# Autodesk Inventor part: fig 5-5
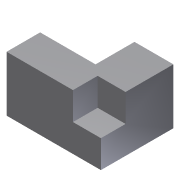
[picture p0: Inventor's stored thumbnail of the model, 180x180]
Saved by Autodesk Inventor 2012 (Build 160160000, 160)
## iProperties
Created: 2010-02
Part Number: fig 5-5
Document SubType Name: Modeling
Designer: CADSoft
Density: 1 g/cm^3
Material: Default
Author: CADSoft
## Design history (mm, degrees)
sketch "Sketch1"
  geometry: L1 (0, 26.227)-(0, 12.145); L2 (0, 12.145)-(-20.026, 12.145); L3 (-20.026, 12.145)-(-20.026, 0); L4 (-20.026, 0)-(14.083, 0); L5 (14.083, 0)-(14.083, 26.227); L6 (14.083, 26.227)-(0, 26.227); 1 further point
  constraints: 12 end point
extrude "Extrusion1" new body sketch "Sketch1" distance "d0" = 20; taper "d1" = 0 deg
sketch "Sketch2"
  geometry: L1 (14.083, 0)-(3.983, 0); L2 (3.983, 0)-(3.983, 8.922); L3 (3.983, 8.922)-(14.083, 8.922); L4 (14.083, 8.922)-(14.083, 0); 1 further point
  constraints: 8 end point
extrude "Extrusion2" cut sketch "Sketch2" distance "d2" = 10; taper "d3" = 0 deg
body "Solid1"
